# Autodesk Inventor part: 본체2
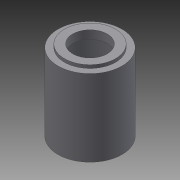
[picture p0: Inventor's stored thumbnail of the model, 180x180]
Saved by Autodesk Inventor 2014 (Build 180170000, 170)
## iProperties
Created: 2015-10
Part Number: 본체2
Material: 일반
Document SubType Name: Modeling
Designer: USER
Density: 1 g/cm^3
Appearance: 기본값
Author: USER
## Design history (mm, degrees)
sketch "스케치1"
  geometry: C1 r 50 at (0, 0); 1 further point
  constraints: 1 centre point, 1 coincident
  dimensions: "d0" = 100 diameter of C1
extrude "돌출1" new body sketch "스케치1" distance "d1" = 120; taper "d2" = 0 deg
sketch "스케치2"
  geometry: C1 r 50 at (0, 0) reference; C2 r 40 at (0, 0)
  constraints: 1 centre point, 1 coincident
  dimensions: "d3" = 80 diameter of C2
extrude "돌출2" join sketch "스케치2" distance "d4" = 5; taper "d5" = 0 deg
sketch "스케치3"
  geometry: C1 r 40 at (0, 0) reference; C2 r 27 at (0, 0)
  constraints: 1 centre point, 1 coincident
  dimensions: "d6" = 54 diameter of C2
extrude "돌출3" cut sketch "스케치3" distance "d7" = 13; taper "d8" = 0 deg
sketch "스케치4"
  geometry: C1 r 27 at (0, 0) reference; C2 r 45 at (0, 0)
  constraints: 1 centre point, 1 coincident
  dimensions: "d9" = 90 diameter of C2
extrude "돌출4" cut sketch "스케치4" distance "d10" = 112; taper "d11" = 0 deg
node "솔리드1"
